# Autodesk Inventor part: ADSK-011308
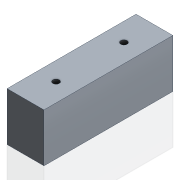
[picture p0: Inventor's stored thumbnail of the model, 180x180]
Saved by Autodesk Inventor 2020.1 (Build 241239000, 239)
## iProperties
Created: 1999-11
Part Number: ADSK-011308
Material: Pearson Aluminium
Description: PLT-04,FA,CP,15,020,052,POST,MNT,BEARING
Document SubType Name: Modeling
Designer: sspink
Density: 2.71 g/cm^3
Appearance: Pearson-Aluminum
Mass: 672.113 g
Surface Area: 296.018 cm^2
Volume: 248.012 cm^3
Control State: 0
Checked Out: False
Last Check In By: sspink
Last Check In Date: 1999-12-16
Master: False
Shininess: 35.0
Length Units: 11269
Angle Units: 11279
Time Units: 11290
Mass Units: 11283
Length Display Precision: 3
Angle Display Precision: 2
Compacted: True
Material Desc: FLAT,ALUM, 1.50 X 2.00
Cutlength: 5.25
Material_number: A093038
Dimensions: 38x50x133 mm
Mass: 0,672 kg
DocNumber: ADSK-011308.ipt
Folder: 01 - Themengebiete\Simplification\01 - Packaging machine\
VDS_Category: 3D Komponenten
Density: 2.71
Volumn: 254.00477217175793
Area: 296.346909758565
PropertySet Name: Model Information
Author: sspink
Revision Number: -
Title: PLT-04,FA,CP,15,020,052,POST,MNT,BEARING
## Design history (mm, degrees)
node "Solide1"
  node "Extrusion1" dims "d2" = 133, "d3" = 0
  node "Hole1" dims "d4" = 8.376, "d5" = 9.525, "d6" = 6.35, "d7" = 60 deg, "d8" = 27.3, "d9" = 118 deg, "d33" = 20
  node "Hole3" dims "d24" = 6.647, "d25" = 9.525, "d26" = 6.35, "d27" = 60 deg, "d28" = 22.2, "d29" = 118 deg, "d35" = 16
sketch "Sketch1"
  geometry: L1 (-19, 25)-(19, 25); L2 (19, 25)-(19, -25); L3 (19, -25)-(-19, -25); L4 (-19, -25)-(-19, 25); 3 further points
  constraints: 8 end point, 2 midpoint, 2 parallel, 1 horizontal, 1 horizontal alignment, 1 perpendicular, 1 vertical alignment
  dimensions: "d0" = 50 distance of L1.end L2.end; "d1" = 38 distance of L2.end L3.end
sketch "Sketch2"
  geometry: L1 (0, 0)-(38, 0) reference; L2 (19, 20.5)-(19, 112.5); L3 (0, 0)-(0, 133) reference; 3 further points
  constraints: 3 midpoint, 2 end point, 1 horizontal alignment, 1 vertical, 1 vertical alignment
  dimensions: "d32" = 92 distance of L2.start L2.end
sketch "Sketch4"
  geometry: L1 (0, -133)-(38, -133) reference; L2 (19, -101.5)-(19, -31.5); L3 (0, -133)-(0, 0) reference; 3 further points
  constraints: 3 midpoint, 2 end point, 1 horizontal alignment, 1 vertical, 1 vertical alignment
  dimensions: "d34" = 70 distance of L2.start L2.end
node "Corps solides"
node "Corps surfaciques"
